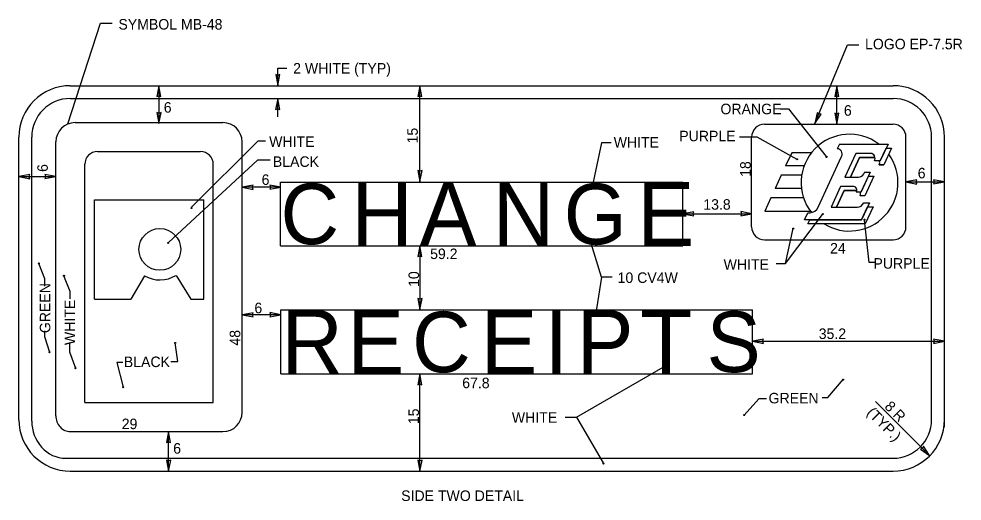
# Model space of a CAD drawing. Extents: x 319706 to 320346, y 1621790 to 1622121.
# Drawn here: x 320220.4 to 320345.9, y 1621873.5 to 1621937.7 of the extents above; entities that cross this region are included whole.
import ezdxf

# ---------------------------------------------------------------- set-up
doc = ezdxf.new("R2010")
doc.units = 0
for name, color, linetype in [('1', 7, 'Continuous'), ('52', 7, 'Continuous'), ('SignPanel', 7, 'Continuous'), ('SOILS_SP83_SHP', 7, 'Continuous')]:
    doc.layers.add(name, color=color, linetype=linetype)

msp = doc.modelspace()

# ---------------------------------------------------------------- linework, layer by layer
at = {"layer": '1'}
for p, q in [((320226.94, 1621923.71), (320231.26, 1621937.15)), ((320231.26, 1621937.15), (320232.81, 1621937.15)), ((320326.31, 1621923.76), (320330.66, 1621934.26)), ((320330.66, 1621934.26), (320332.16, 1621934.26)), ((320254.85, 1621928.83), (320254.85, 1621931.14)), ((320254.85, 1621931.14), (320256.08, 1621931.14)), ((320329.22, 1621923.68), (320329.22, 1621928.81)), ((320254.85, 1621924.68), (320254.85, 1621927.08)), ((320321.67, 1621925.73), (320322.81, 1621925.73)), ((320322.81, 1621925.73), (320327.8, 1621919.37)), ((320316.28, 1621922), (320318.56, 1621922)), ((320318.56, 1621922), (320323.89, 1621919.04)), ((320252.21, 1621921.42), (320243.39, 1621912.62)), ((320253.21, 1621921.42), (320252.21, 1621921.42)), ((320297.91, 1621921.19), (320296.68, 1621915.33)), ((320299.19, 1621921.19), (320297.91, 1621921.19)), ((320252.15, 1621918.89), (320240.33, 1621907.93)), ((320253.83, 1621918.89), (320252.15, 1621918.89)), ((320338.41, 1621916), (320343.54, 1621916)), ((320322.41, 1621905.16), (320327.32, 1621911.65)), ((320333.5, 1621905.28), (320332.92, 1621910.89)), ((320322.41, 1621905.16), (320323.42, 1621909.78)), ((320297.91, 1621903.34), (320296.41, 1621908.24)), ((320223.88, 1621903.1), (320223.07, 1621905.15)), ((320321.13, 1621905.16), (320322.41, 1621905.16)), ((320334.26, 1621905.28), (320333.5, 1621905.28)), ((320227.23, 1621901.39), (320226.42, 1621903.51)), ((320297.91, 1621903.34), (320297.1, 1621898.24)), ((320299.35, 1621903.34), (320297.91, 1621903.34)), ((320223.88, 1621902.14), (320223.88, 1621903.1)), ((320227.23, 1621900.43), (320227.23, 1621901.39)), ((320223.82, 1621896.18), (320223.82, 1621895.44)), ((320223.82, 1621895.44), (320224.5, 1621893.32)), ((320227.16, 1621894.49), (320227.16, 1621893.39)), ((320241.58, 1621892.1), (320241.21, 1621894.56)), ((320227.16, 1621893.39), (320227.97, 1621891.21)), ((320234.25, 1621891.96), (320233.45, 1621891.96)), ((320233.45, 1621891.96), (320234.31, 1621888.68)), ((320240.65, 1621892.1), (320241.58, 1621892.1)), ((320294.6, 1621884.7), (320306.44, 1621891.51)), ((320328.03, 1621887.3), (320330.06, 1621889.69)), ((320318.86, 1621887.12), (320316.9, 1621884.96)), ((320319.88, 1621887.12), (320318.86, 1621887.12)), ((320327.29, 1621887.3), (320328.03, 1621887.3)), ((320341.56, 1621879.6), (320334.36, 1621886.79)), ((320293.07, 1621884.7), (320294.6, 1621884.7)), ((320294.6, 1621884.7), (320298.2, 1621878.51))]:
    msp.add_line(p, q, dxfattribs=at)
for centre, major_axis, ratio in [((320323.93, 1621919.02), (0, 0.0707), 0.906668), ((320327.85, 1621919.32), (0, 0.0707), 0.906668), ((320296.65, 1621915.25), (0.0736, 0), 0.960359), ((320243.4, 1621912.52), (0, 0.0707), 0.906668), ((320327.37, 1621911.71), (0, 0.0707), 0.906668), ((320332.91, 1621910.97), (0, 0.0707), 0.906668), ((320323.42, 1621909.78), (0, 0.0707), 0.906668), ((320296.37, 1621908.27), (0.0736, 0), 0.960359), ((320240.28, 1621907.88), (0, 0.0707), 0.906668), ((320223.07, 1621905.15), (0, 0.0707), 0.906668), ((320226.42, 1621903.51), (0, 0.0707), 0.906668), ((320297.02, 1621898.22), (0.0736, 0), 0.961364), ((320241.21, 1621894.56), (0, 0.0707), 0.906668), ((320224.5, 1621893.32), (0, 0.0707), 0.906668), ((320227.97, 1621891.2), (0, 0.0707), 0.906668), ((320306.4, 1621891.51), (0.0736, 0), 0.961364), ((320330.06, 1621889.68), (0, 0.0707), 0.906668), ((320234.31, 1621888.68), (0, 0.0707), 0.906668), ((320316.9, 1621884.96), (0, 0.0707), 0.906668), ((320298.2, 1621878.51), (0, 0.0707), 0.906668)]:
    msp.add_ellipse(centre, major_axis=major_axis, ratio=ratio, dxfattribs=at)
at = {"layer": '52'}
for p, q in [((320254.85, 1621930.17), (320254.58, 1621930.28)), ((320254.58, 1621930.28), (320254.85, 1621928.83)), ((320254.85, 1621928.83), (320255.13, 1621930.28)), ((320255.13, 1621930.28), (320254.85, 1621930.17)), ((320239.05, 1621928.81), (320238.77, 1621927.36)), ((320239.32, 1621927.36), (320239.05, 1621928.81)), ((320273.76, 1621928.81), (320273.48, 1621927.36)), ((320274.03, 1621927.36), (320273.76, 1621928.81)), ((320329.22, 1621928.81), (320328.94, 1621927.36)), ((320329.49, 1621927.36), (320329.22, 1621928.81)), ((320238.77, 1621927.36), (320239.05, 1621927.47)), ((320239.05, 1621927.47), (320239.32, 1621927.36)), ((320254.85, 1621927.08), (320254.57, 1621925.63)), ((320255.12, 1621925.63), (320254.85, 1621927.08)), ((320273.48, 1621927.36), (320273.76, 1621927.47)), ((320273.76, 1621927.47), (320274.03, 1621927.36)), ((320328.94, 1621927.36), (320329.22, 1621927.47)), ((320329.22, 1621927.47), (320329.49, 1621927.36)), ((320239.05, 1621925.12), (320238.78, 1621925.23)), ((320238.78, 1621925.23), (320239.05, 1621923.78)), ((320239.05, 1621923.78), (320239.33, 1621925.23)), ((320239.33, 1621925.23), (320239.05, 1621925.12)), ((320254.57, 1621925.63), (320254.85, 1621925.74)), ((320254.85, 1621925.74), (320255.12, 1621925.63)), ((320326.62, 1621925.21), (320326.31, 1621923.76)), ((320326.31, 1621923.76), (320327.12, 1621925)), ((320326.82, 1621925), (320326.62, 1621925.21)), ((320327.12, 1621925), (320326.82, 1621925)), ((320329.22, 1621925.02), (320328.95, 1621925.13)), ((320328.95, 1621925.13), (320329.22, 1621923.68)), ((320329.22, 1621923.68), (320329.5, 1621925.13)), ((320329.5, 1621925.13), (320329.22, 1621925.02)), ((320221.87, 1621916.98), (320220.42, 1621916.71)), ((320221.76, 1621916.71), (320221.87, 1621916.98)), ((320225.33, 1621916.71), (320223.88, 1621916.99)), ((320223.88, 1621916.99), (320223.99, 1621916.71)), ((320273.76, 1621917.41), (320273.49, 1621917.52)), ((320273.49, 1621917.52), (320273.76, 1621916.07)), ((320273.76, 1621916.07), (320274.04, 1621917.52)), ((320274.04, 1621917.52), (320273.76, 1621917.41)), ((320220.42, 1621916.71), (320221.87, 1621916.43)), ((320221.87, 1621916.43), (320221.76, 1621916.71)), ((320223.99, 1621916.71), (320223.88, 1621916.44)), ((320223.88, 1621916.44), (320225.33, 1621916.71)), ((320339.86, 1621916.27), (320338.41, 1621916)), ((320338.41, 1621916), (320339.86, 1621915.72)), ((320339.75, 1621916), (320339.86, 1621916.27)), ((320339.86, 1621915.72), (320339.75, 1621916)), ((320343.54, 1621916), (320342.09, 1621916.28)), ((320342.09, 1621916.28), (320342.2, 1621916)), ((320342.2, 1621916), (320342.09, 1621915.73)), ((320342.09, 1621915.73), (320343.54, 1621916)), ((320251.58, 1621915.56), (320250.13, 1621915.29)), ((320250.13, 1621915.29), (320251.58, 1621915.01)), ((320251.47, 1621915.29), (320251.58, 1621915.56)), ((320251.58, 1621915.01), (320251.47, 1621915.29)), ((320255.27, 1621915.29), (320253.82, 1621915.57)), ((320253.82, 1621915.57), (320253.93, 1621915.29)), ((320253.93, 1621915.29), (320253.82, 1621915.02)), ((320253.82, 1621915.02), (320255.27, 1621915.29)), ((320310.19, 1621912.03), (320308.74, 1621911.76)), ((320310.08, 1621911.76), (320310.19, 1621912.03)), ((320317.89, 1621911.76), (320316.44, 1621912.04)), ((320316.44, 1621912.04), (320316.55, 1621911.76)), ((320308.74, 1621911.76), (320310.19, 1621911.48)), ((320310.19, 1621911.48), (320310.08, 1621911.76)), ((320316.55, 1621911.76), (320316.44, 1621911.49)), ((320316.44, 1621911.49), (320317.89, 1621911.76)), ((320273.76, 1621907.51), (320273.48, 1621906.06)), ((320274.03, 1621906.06), (320273.76, 1621907.51)), ((320273.48, 1621906.06), (320273.76, 1621906.17)), ((320273.76, 1621906.17), (320274.03, 1621906.06)), ((320273.76, 1621900.37), (320273.49, 1621900.48)), ((320273.49, 1621900.48), (320273.76, 1621899.03)), ((320273.76, 1621899.03), (320274.04, 1621900.48)), ((320274.04, 1621900.48), (320273.76, 1621900.37)), ((320251.58, 1621898.59), (320250.13, 1621898.32)), ((320250.13, 1621898.32), (320251.58, 1621898.04)), ((320251.47, 1621898.32), (320251.58, 1621898.59)), ((320251.58, 1621898.04), (320251.47, 1621898.32)), ((320255.26, 1621898.32), (320253.81, 1621898.6)), ((320253.81, 1621898.6), (320253.92, 1621898.32)), ((320253.92, 1621898.32), (320253.81, 1621898.05)), ((320253.81, 1621898.05), (320255.26, 1621898.32)), ((320319.46, 1621895.05), (320318.01, 1621894.78)), ((320318.01, 1621894.78), (320319.46, 1621894.5)), ((320319.35, 1621894.78), (320319.46, 1621895.05)), ((320319.46, 1621894.5), (320319.35, 1621894.78)), ((320343.54, 1621894.78), (320342.09, 1621895.06)), ((320342.09, 1621895.06), (320342.2, 1621894.78)), ((320342.2, 1621894.78), (320342.09, 1621894.51)), ((320342.09, 1621894.51), (320343.54, 1621894.78)), ((320273.76, 1621890.46), (320273.48, 1621889.01)), ((320274.03, 1621889.01), (320273.76, 1621890.46)), ((320273.48, 1621889.01), (320273.76, 1621889.12)), ((320273.76, 1621889.12), (320274.03, 1621889.01)), ((320240.33, 1621882.76), (320240.05, 1621881.31)), ((320240.6, 1621881.31), (320240.33, 1621882.76)), ((320240.05, 1621881.31), (320240.33, 1621881.42)), ((320240.33, 1621881.42), (320240.6, 1621881.31)), ((320340.73, 1621880.82), (320340.61, 1621880.54)), ((320341.56, 1621879.6), (320340.73, 1621880.82)), ((320340.61, 1621880.54), (320340.34, 1621880.43)), ((320340.34, 1621880.43), (320341.56, 1621879.6)), ((320240.33, 1621878.85), (320240.06, 1621878.96)), ((320240.06, 1621878.96), (320240.33, 1621877.51)), ((320240.33, 1621877.51), (320240.61, 1621878.96)), ((320240.61, 1621878.96), (320240.33, 1621878.85)), ((320273.76, 1621878.85), (320273.49, 1621878.96)), ((320273.49, 1621878.96), (320273.76, 1621877.51)), ((320273.76, 1621877.51), (320274.04, 1621878.96)), ((320274.04, 1621878.96), (320273.76, 1621878.85))]:
    msp.add_line(p, q, dxfattribs=at)
at = {"layer": 'SignPanel'}
for p, q in [((320227.26, 1621928.81), (320336.7, 1621928.81)), ((320239.05, 1621928.81), (320239.05, 1621923.78)), ((320273.76, 1621916.07), (320273.76, 1621928.81)), ((320227.26, 1621927.1), (320336.7, 1621927.1)), ((320227.9, 1621923.89), (320247.56, 1621923.89)), ((320319.6, 1621923.68), (320336.7, 1621923.68)), ((320220.42, 1621884.35), (320220.42, 1621921.97)), ((320222.13, 1621884.17), (320222.13, 1621921.97)), ((320225.33, 1621884.88), (320225.33, 1621921.33)), ((320250.13, 1621885.32), (320250.13, 1621921.33)), ((320317.89, 1621910), (320317.89, 1621921.97)), ((320329.56, 1621921.04), (320329.27, 1621920.41)), ((320329.56, 1621921.04), (320336.04, 1621921.04)), ((320336.04, 1621921.04), (320335, 1621918.79)), ((320338.41, 1621910), (320338.41, 1621921.97)), ((320341.83, 1621884.35), (320341.83, 1621921.97)), ((320343.54, 1621883.34), (320343.54, 1621921.97)), ((320230.89, 1621920.05), (320244.57, 1621920.05)), ((320323.22, 1621919.89), (320322.4, 1621918.12)), ((320325.86, 1621919.89), (320323.22, 1621919.89)), ((320331.76, 1621919.78), (320330.3, 1621916.63)), ((320331.76, 1621919.78), (320330.3, 1621916.63)), ((320333.7, 1621919.78), (320331.76, 1621919.78)), ((320333.7, 1621919.78), (320331.76, 1621919.78)), ((320335, 1621918.79), (320335.79, 1621920.51)), ((320336.51, 1621920.51), (320335.47, 1621918.26)), ((320336.51, 1621920.51), (320335.47, 1621918.26)), ((320335.79, 1621920.51), (320336.51, 1621920.51)), ((320335.79, 1621920.51), (320336.51, 1621920.51)), ((320229.18, 1621886.65), (320229.18, 1621918.34)), ((320246.28, 1621886.65), (320246.28, 1621918.34)), ((320326.75, 1621912.63), (320329.86, 1621919.38)), ((320332.23, 1621919.25), (320331.02, 1621916.63)), ((320331.02, 1621916.63), (320332.23, 1621919.25)), ((320334.29, 1621919.25), (320332.23, 1621919.25)), ((320332.23, 1621919.25), (320334.29, 1621919.25)), ((320335, 1621918.79), (320334.24, 1621918.79)), ((320334.85, 1621918.26), (320335.47, 1621918.26)), ((320335.47, 1621918.26), (320334.85, 1621918.26)), ((320334.88, 1621918.79), (320335, 1621918.79)), ((320324.87, 1621918.12), (320322.4, 1621918.12)), ((320333.67, 1621917.31), (320332.46, 1621914.69)), ((320332.9, 1621917.31), (320332.8, 1621917.09)), ((320332.9, 1621917.31), (320333.67, 1621917.31)), ((320220.42, 1621916.71), (320225.33, 1621916.71)), ((320321.83, 1621916.88), (320321.01, 1621915.11)), ((320324.55, 1621916.88), (320321.83, 1621916.88)), ((320330.3, 1621916.63), (320332.12, 1621916.63)), ((320330.3, 1621916.63), (320331.02, 1621916.63)), ((320332.46, 1621914.69), (320333.42, 1621916.78)), ((320334.14, 1621916.78), (320332.93, 1621914.16)), ((320334.14, 1621916.78), (320332.93, 1621914.16)), ((320333.42, 1621916.78), (320334.14, 1621916.78)), ((320333.42, 1621916.78), (320334.14, 1621916.78)), ((320255.27, 1621915.29), (320250.13, 1621915.29)), ((320324.52, 1621915.11), (320321.01, 1621915.11)), ((320329.72, 1621915.37), (320328.46, 1621912.64)), ((320329.72, 1621915.37), (320328.46, 1621912.64)), ((320330.2, 1621914.84), (320329.18, 1621912.64)), ((320329.18, 1621912.64), (320330.2, 1621914.84)), ((320331.48, 1621915.37), (320329.72, 1621915.37)), ((320331.48, 1621915.37), (320329.72, 1621915.37)), ((320331.87, 1621914.84), (320330.2, 1621914.84)), ((320330.2, 1621914.84), (320331.87, 1621914.84)), ((320331.81, 1621914.69), (320332.46, 1621914.69)), ((320332.34, 1621914.69), (320332.46, 1621914.69)), ((320230.46, 1621900.38), (320230.46, 1621913.63)), ((320230.46, 1621913.63), (320245, 1621913.63)), ((320245, 1621900.39), (320245, 1621913.63)), ((320320.44, 1621913.88), (320319.62, 1621912.11)), ((320324.8, 1621913.88), (320320.44, 1621913.88)), ((320332.93, 1621914.16), (320332.31, 1621914.16)), ((320332.93, 1621914.16), (320332.31, 1621914.16)), ((320319.62, 1621912.11), (320325.72, 1621912.11)), ((320328.46, 1621912.64), (320331.95, 1621912.64)), ((320328.46, 1621912.64), (320328.46, 1621912.64)), ((320328.46, 1621912.64), (320329.18, 1621912.64)), ((320333.56, 1621913.21), (320332.52, 1621910.96)), ((320332.52, 1621910.96), (320333.31, 1621912.67)), ((320332.8, 1621913.21), (320333.56, 1621913.21)), ((320334.03, 1621912.67), (320333, 1621910.43)), ((320334.03, 1621912.67), (320333, 1621910.43)), ((320333.31, 1621912.67), (320334.03, 1621912.67)), ((320333.31, 1621912.67), (320334.03, 1621912.67)), ((320308.74, 1621911.76), (320317.89, 1621911.76)), ((320324.91, 1621910.96), (320325.34, 1621911.9)), ((320332.52, 1621910.96), (320324.91, 1621910.96)), ((320325.34, 1621911.9), (320325.66, 1621911.9)), ((320325.38, 1621910.43), (320325.63, 1621910.96)), ((320325.38, 1621910.43), (320325.63, 1621910.96)), ((320325.63, 1621910.96), (320332.52, 1621910.96)), ((320333, 1621910.43), (320325.38, 1621910.43)), ((320333, 1621910.43), (320325.38, 1621910.43)), ((320319.6, 1621908.29), (320336.7, 1621908.29)), ((320273.76, 1621907.51), (320273.76, 1621899.03)), ((320237.12, 1621903.5), (320235.3, 1621900.38)), ((320241.32, 1621903.56), (320243.29, 1621900.39)), ((320230.46, 1621900.38), (320235.3, 1621900.38)), ((320243.29, 1621900.39), (320245, 1621900.39)), ((320255.26, 1621898.32), (320250.13, 1621898.32)), ((320318.01, 1621894.78), (320343.54, 1621894.78)), ((320273.76, 1621877.51), (320273.76, 1621890.46)), ((320229.18, 1621886.65), (320246.28, 1621886.65)), ((320227.26, 1621882.76), (320247.56, 1621882.76)), ((320240.33, 1621877.51), (320240.33, 1621882.76)), ((320226.62, 1621879.22), (320336.7, 1621879.22)), ((320227.26, 1621877.51), (320336.7, 1621877.51))]:
    msp.add_line(p, q, dxfattribs=at)
msp.add_circle((320239.17, 1621907.01), 2.78, dxfattribs=at)
for centre, radius, start, end in [((320227.26, 1621921.97), 6.84, 90, 180), ((320336.7, 1621921.97), 6.84, 0, 90), ((320227.26, 1621921.97), 5.13, 90, 180), ((320336.7, 1621921.97), 5.13, 0, 90), ((320227.9, 1621921.33), 2.56, 90, 180), ((320247.56, 1621921.33), 2.56, 0, 90), ((320319.6, 1621921.97), 1.71, 90, 180), ((320336.7, 1621921.97), 1.71, 0, 90), ((320330.91, 1621915.9), 6.44, 52.9547, 218.1763), ((320230.89, 1621918.34), 1.71, 90, 180), ((320244.57, 1621918.34), 1.71, 0, 90), ((320330.91, 1621915.9), 6.44, 238.1578, 35.8999), ((320319.6, 1621910), 1.71, 180, 270), ((320336.7, 1621910), 1.71, 270, 360), ((320239.17, 1621907.01), 4.06, 239.7206, 301.9049), ((320227.26, 1621884.35), 6.84, 180, 270), ((320247.56, 1621885.32), 2.56, 270, 360), ((320336.7, 1621884.35), 5.13, 270, 0), ((320336.7, 1621884.35), 6.84, 270, 0)]:
    msp.add_arc(centre, radius, start, end, dxfattribs=at)
for centre, major_axis, start_param, end_param in [((320329.29, 1621919.7), (0, 0.707), 4.241328, 6.314398), ((320333.7, 1621919.11), (0, 0.672), 4.227342, 6.283185), ((320333.7, 1621919.11), (0, 0.672), 4.924772, 6.283185), ((320334.31, 1621918.58), (0, 0.672), 4.227342, 5.041732), ((320334.31, 1621918.58), (0, 0.672), 4.227342, 5.041732), ((320332.12, 1621917.47), (0, 0.84), 3.141593, 4.241405), ((320331.48, 1621914.93), (0, 0.442), 4.144801, 6.283185), ((320331.48, 1621914.93), (0, 0.442), 4.511031, 6.283185), ((320331.77, 1621914.47), (0, 0.672), 4.227342, 5.041732), ((320331.77, 1621914.47), (0, 0.672), 4.227342, 5.041732), ((320325.66, 1621913.24), (0, 1.34), 3.141593, 4.241135), ((320331.95, 1621913.69), (0, 1.05), 3.141593, 4.232591), ((320227.26, 1621884.88), (0, 2.12), 1.570796, 3.141593), ((320226.62, 1621884.17), (0, 4.95), 1.570796, 3.141593)]:
    msp.add_ellipse(centre, major_axis=major_axis, ratio=0.906668, start_param=start_param, end_param=end_param, dxfattribs=at)
at = {"layer": 'SOILS_SP83_SHP'}
for p, q in [((320255.21, 1621915.98), (320308.74, 1621915.98)), ((320255.21, 1621907.5), (320255.21, 1621915.98)), ((320308.74, 1621907.5), (320308.74, 1621915.98)), ((320255.21, 1621907.5), (320308.74, 1621907.5)), ((320255.26, 1621898.95), (320318.01, 1621898.95)), ((320255.26, 1621890.46), (320255.26, 1621898.95)), ((320318.01, 1621890.46), (320318.01, 1621898.95)), ((320255.26, 1621890.46), (320318.01, 1621890.46))]:
    msp.add_line(p, q, dxfattribs=at)

# ---------------------------------------------------------------- texts
at = {"layer": '1'}
for s, p in [('SYMBOL MB-48', (320233.66, 1621936.28)), ('LOGO EP-7.5R', (320332.97, 1621933.65)), ('2 WHITE (TYP)', (320256.9, 1621930.42)), ('ORANGE', (320313.74, 1621925.01)), ('6', (320330.16, 1621924.81)), ('WHITE', (320253.71, 1621920.66)), ('PURPLE', (320308.26, 1621921.41)), ('WHITE', (320299.54, 1621920.57)), ('BLACK', (320254.2, 1621918)), ('6', (320252.71, 1621915.6)), ('6', (320339.98, 1621916.47)), ('13.8', (320311.46, 1621912.3)), ('59.2', (320275.12, 1621905.73)), ('24', (320328.32, 1621906.47)), ('WHITE', (320314.16, 1621904.3)), ('PURPLE', (320334.09, 1621904.45)), ('10 CV4W', (320300.06, 1621902.55)), ('6', (320251.75, 1621898.52)), ('35.2', (320326.81, 1621895.09)), ('BLACK', (320234.38, 1621891.35)), ('67.8', (320279.39, 1621888.54)), ('GREEN', (320320.14, 1621886.52)), ('29', (320234.1, 1621883.09)), ('WHITE', (320285.99, 1621883.94)), ('SIDE TWO DETAIL', (320271.27, 1621873.53))]:
    msp.add_text(s, height=1.4, dxfattribs=at).set_placement(p)
for s, rotation, p in [('15', 90, (320273.48, 1621921.12)), ('18', 90, (320317.76, 1621916.67)), ('10', 90, (320273.65, 1621902.02)), ('GREEN', 90, (320224.6, 1621895.87)), ('WHITE', 90, (320227.9, 1621894.28)), ('48', 90, (320249.86, 1621894.21)), ('15', 90, (320273.63, 1621883.75)), ('(TYP.)', 315, (320333.1, 1621885.17)), ('8 R', 315, (320335.47, 1621885.99))]:
    msp.add_text(s, height=1.4, rotation=rotation, dxfattribs=at).set_placement(p)
at = {"layer": 'SignPanel'}
for s, height, p in [('6', 1.4, (320239.69, 1621925.22)), ('C', 8.06, (320255.23, 1621907.71)), ('H', 8.49, (320264.63, 1621907.47)), ('A', 8.49, (320273.72, 1621907.49)), ('N', 8.49, (320283.46, 1621907.44)), ('G', 8.06, (320292.9, 1621907.69)), ('E', 8.49, (320302.68, 1621907.49)), ('R', 8.49, (320255.32, 1621890.48)), ('E', 8.49, (320264.1, 1621890.44)), ('C', 8.06, (320272.73, 1621890.66)), ('E', 8.49, (320281.83, 1621890.44)), ('I', 8.49, (320290.35, 1621890.44)), ('P', 8.49, (320294.61, 1621890.45)), ('T', 8.49, (320303.04, 1621890.48)), ('S', 8.06, (320311.9, 1621890.68)), ('6', 1.4, (320240.95, 1621879.83))]:
    msp.add_text(s, height=height, dxfattribs=at).set_placement(p)
msp.add_text('6', height=1.4, rotation=90, dxfattribs=at).set_placement((320224.27, 1621917.33))

doc.saveas('drawing.dxf')
